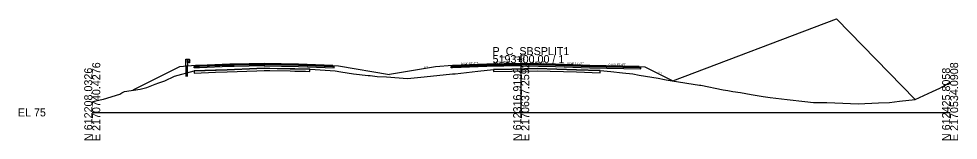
# Model space of a CAD drawing. Extents: x -26 to 1303, y -3010 to 12033.
# Drawn here: x -25.7 to 302.8, y 10990.3 to 11032.7 of the extents above; entities that cross this region are included whole.
import ezdxf

# ---------------------------------------------------------------- set-up
doc = ezdxf.new("R2010")
doc.units = 0
for name, color, linetype in [('RD_GPK_XS_Cell', 7, 'Continuous'), ('RD_PD_Final_TrvlWay', 7, 'Continuous'), ('RD_Sketch10', 7, 'Continuous'), ('RD_XS_Base', 7, 'Continuous'), ('RD_XS_ExGround', 7, 'Continuous'), ('RD_XS_ExPaveRet', 7, 'Continuous'), ('RD_XS_GR', 7, 'Continuous'), ('RD_XS_Greenside', 7, 'Continuous'), ('RD_XS_Pave', 7, 'Continuous'), ('RD_XS_PaveOvlay_CP', 7, 'Continuous'), ('RD_XS_TieSlope', 7, 'Continuous'), ('RD_XS_TX_Elev_EX', 7, 'Continuous'), ('RD_XS_TX_Elev_PR', 7, 'Continuous'), ('RD_XS_TX_Slope', 7, 'Continuous')]:
    doc.layers.add(name, color=color, linetype=linetype)

msp = doc.modelspace()

# ---------------------------------------------------------------- linework, layer by layer
at = {"layer": 'RD_GPK_XS_Cell'}
for p, q in [((150, 11000), (150, 11020)), ((0, 11000), (150, 11000)), ((150, 11000), (300, 11000))]:
    msp.add_line(p, q, dxfattribs=at)
at = {"layer": 'RD_PD_Final_TrvlWay'}
msp.add_lwpolyline([(33.27, 11012.54), (33.27, 11016.15), (32.77, 11016.11), (32.77, 11012.54)], dxfattribs=at)
at = {"layer": 'RD_Sketch10'}
msp.add_lwpolyline([(203.09, 11010.97), (260.24, 11032.67), (287.83, 11004.51)], dxfattribs=at)
at = {"layer": 'RD_XS_Base'}
for p, q in [((35.61, 11015.59), (35.61, 11016.04)), ((35.61, 11016.04), (35.67, 11016.04)), ((35.67, 11016.04), (36.11, 11016.06)), ((36.11, 11016.06), (37.5, 11016.11)), ((37.5, 11016.11), (48.11, 11016.53)), ((48.11, 11016.03), (37.5, 11015.61)), ((48.11, 11016.53), (49.67, 11016.57)), ((49.67, 11016.07), (48.11, 11016.03)), ((49.67, 11016.57), (60.11, 11016.77)), ((60.11, 11016.27), (49.67, 11016.07)), ((60.11, 11016.8), (60.11, 11016.93)), ((60.11, 11016.93), (60.11, 11016.37)), ((60.11, 11016.77), (60.11, 11016.93)), ((60.11, 11016.93), (60.11, 11016.27)), ((60.11, 11016.77), (60.11, 11016.8)), ((60.11, 11016.77), (60.11, 11016.35)), ((60.11, 11016.77), (60.11, 11016.27)), ((72.11, 11016.53), (60.11, 11016.77)), ((60.11, 11016.77), (60.11, 11016.77)), ((60.11, 11016.37), (60.11, 11016.27)), ((60.11, 11016.35), (60.11, 11016.27)), ((60.11, 11016.27), (60.11, 11016.27)), ((60.11, 11016.27), (60.11, 11016.27)), ((60.11, 11016.27), (72.11, 11016.03)), ((84.11, 11016.05), (72.11, 11016.53)), ((72.11, 11016.03), (84.61, 11015.53)), ((74.11, 11016.45), (74.11, 11016.45)), ((74.11, 11015.95), (74.11, 11015.95)), ((84.61, 11016.03), (84.11, 11016.05)), ((84.11, 11016.05), (84.11, 11016.05)), ((84.61, 11015.53), (84.61, 11016.03)), ((84.61, 11016.03), (84.61, 11016.03)), ((125.5, 11016.04), (126, 11016.06)), ((125.5, 11015.54), (125.5, 11016.04)), ((125.5, 11016.04), (125.5, 11016.04)), ((126, 11016.06), (138, 11016.54)), ((126, 11016.06), (126, 11016.06)), ((138, 11016.04), (126, 11015.56)), ((136, 11016.46), (136, 11016.46)), ((136, 11015.96), (136, 11015.96)), ((138, 11016.54), (150, 11016.78)), ((150, 11016.28), (138, 11016.04)), ((150, 11016.78), (150, 11016.94)), ((150, 11016.94), (150, 11016.28)), ((150, 11016.78), (150, 11016.78)), ((162, 11016.54), (150, 11016.78)), ((150, 11016.78), (150, 11016.78)), ((150, 11016.78), (150, 11016.28)), ((150, 11016.28), (150, 11016.28)), ((150, 11016.28), (162, 11016.04)), ((150, 11016.28), (150, 11016.28)), ((174, 11016.06), (162, 11016.54)), ((162, 11016.54), (162, 11016.54)), ((162, 11016.04), (162, 11016.04)), ((162, 11016.04), (174, 11015.56)), ((191.3, 11015.71), (174, 11016.06)), ((174, 11016.06), (174, 11016.06)), ((191.8, 11015.7), (191.3, 11015.71)), ((191.3, 11015.71), (191.3, 11015.71)), ((191.8, 11015.2), (191.8, 11015.7)), ((191.8, 11015.7), (191.8, 11015.7)), ((35.61, 11015.54), (35.61, 11015.59)), ((35.67, 11015.54), (35.61, 11015.54)), ((36.11, 11015.56), (35.67, 11015.54)), ((37.5, 11015.61), (36.11, 11015.56)), ((84.61, 11015.53), (84.61, 11015.53)), ((84.61, 11015.53), (84.61, 11015.53)), ((126, 11015.56), (125.5, 11015.54)), ((125.5, 11015.54), (125.5, 11015.54)), ((125.5, 11015.54), (125.5, 11015.54)), ((126, 11015.56), (126, 11015.56)), ((174, 11015.56), (174, 11015.56)), ((174, 11015.56), (191.8, 11015.2)), ((191.8, 11015.2), (191.8, 11015.2)), ((191.8, 11015.2), (191.8, 11015.2))]:
    msp.add_line(p, q, dxfattribs=at)
at = {"layer": 'RD_XS_ExGround'}
msp.add_lwpolyline([(0, 11003.73), (0.79, 11003.96), (2.79, 11004.34), (3.91, 11004.68), (9.65, 11006.39), (10.37, 11006.81), (10.56, 11006.9), (11.31, 11007.34), (16.71, 11008.17), (19.09, 11008.71), (22.04, 11009.82), (23.3, 11010.31), (25.38, 11011.03), (28.76, 11012.62), (35.68, 11014.46), (47.19, 11014.92), (60.12, 11015.4), (69.27, 11015.21), (76.14, 11015.07), (76.15, 11015.07), (84.95, 11014.48), (86.89, 11014.18), (91.31, 11013.5), (96.5, 11012.93), (97.15, 11012.85), (99.69, 11012.57), (102.89, 11012.43), (110.27, 11011.84), (116.03, 11012.41), (125.97, 11013.43), (126.55, 11013.47), (126.89, 11013.5), (134.83, 11014.34), (140.29, 11014.99), (146.7, 11015.1), (155.59, 11015.29), (169.3, 11014.87), (177.59, 11014.62), (181.4, 11014.23), (185.48, 11013.83), (189.04, 11013.5), (191.3, 11012.99), (197.93, 11011.9), (200.12, 11011.5), (200.7, 11011.37), (202.79, 11011.02), (212.36, 11009.52), (212.78, 11009.46), (220.69, 11007.9), (222.28, 11007.62), (224.05, 11007.3), (226.72, 11007), (230.4, 11006.28), (234.59, 11005.51), (237.06, 11005.15), (243.04, 11004.5), (249.16, 11003.79), (252.25, 11003.5), (256.89, 11003.41), (262.51, 11003.19), (267.9, 11003.05), (274.99, 11003.33), (278.83, 11003.5), (282.31, 11003.89), (287.83, 11004.51), (293.9, 11007.32), (296.44, 11008.51), (298.06, 11009.37), (300, 11010.59)], dxfattribs=at)
at = {"layer": 'RD_XS_ExPaveRet'}
for points in [[(76.14, 11015.07), (76.14, 11015.07), (74.59, 11015.1), (70.83, 11015.18), (69.27, 11015.21), (62.05, 11015.36), (60.12, 11015.4), (57.56, 11015.31), (47.19, 11014.92), (43.15, 11014.76), (35.68, 11014.46), (35.68, 11013.89), (35.68, 11013.71), (43.15, 11014.01), (47.19, 11014.17), (57.56, 11014.56), (60.12, 11014.65), (62.05, 11014.61), (69.27, 11014.46), (70.83, 11014.43), (74.59, 11014.35), (76.14, 11014.32), (76.14, 11014.32), (76.14, 11014.32), (76.14, 11014.82), (76.14, 11015.07), (76.14, 11015.07)], [(76.14, 11015.07), (74.59, 11015.1), (70.83, 11015.18), (69.27, 11015.21), (62.05, 11015.36), (60.12, 11015.4), (57.56, 11015.31), (47.19, 11014.92), (43.15, 11014.76), (35.68, 11014.46), (35.68, 11013.89), (35.68, 11013.71), (43.15, 11014.01), (47.19, 11014.17), (57.56, 11014.56), (60.12, 11014.65), (62.05, 11014.61), (69.27, 11014.46), (70.83, 11014.43), (74.59, 11014.35), (76.14, 11014.32), (76.14, 11014.82), (76.14, 11015.07)], [(169.3, 11014.87), (155.59, 11015.29), (155.59, 11015.29), (155.59, 11015.29), (146.7, 11015.1), (146.7, 11015.1), (140.29, 11014.99), (140.29, 11014.99), (140.29, 11014.24), (146.7, 11014.35), (146.7, 11014.35), (155.59, 11014.54), (155.59, 11014.54), (155.59, 11014.54), (169.3, 11014.12), (169.3, 11014.12), (177.59, 11013.87), (177.59, 11014.62), (177.59, 11014.62), (169.3, 11014.87), (169.3, 11014.87)], [(169.3, 11014.87), (155.59, 11015.29), (146.7, 11015.1), (140.29, 11014.99), (140.29, 11014.24), (146.7, 11014.35), (155.59, 11014.54), (169.3, 11014.12), (177.59, 11013.87), (177.59, 11014.62), (169.3, 11014.87)]]:
    msp.add_lwpolyline(points, dxfattribs=at)
at = {"layer": 'RD_XS_GR'}
for p, q in [((32.77, 11016.11), (32.77, 11018.54)), ((32.77, 11018.54), (33.02, 11018.54)), ((33.27, 11016.15), (32.77, 11016.11)), ((33.02, 11018.54), (33.27, 11018.54)), ((33.27, 11018.54), (33.27, 11016.15)), ((33.27, 11017.37), (33.27, 11018.54)), ((33.27, 11018.54), (33.94, 11018.54)), ((33.94, 11017.37), (33.27, 11017.37)), ((33.94, 11018.54), (33.94, 11017.37)), ((34.18, 11018.28), (33.94, 11018.54)), ((33.94, 11018.54), (33.94, 11017.51)), ((33.94, 11017.96), (33.97, 11017.99)), ((34.18, 11017.7), (33.94, 11017.96)), ((33.94, 11017.51), (33.94, 11017.37)), ((33.94, 11017.37), (33.97, 11017.41)), ((33.97, 11017.99), (34.21, 11018.25)), ((33.97, 11017.41), (34.21, 11017.67)), ((34.21, 11018.25), (34.18, 11018.28)), ((34.21, 11017.67), (34.18, 11017.7))]:
    msp.add_line(p, q, dxfattribs=at)
at = {"layer": 'RD_XS_Greenside'}
for p, q in [((30.46, 11015.92), (14.15, 11007.77)), ((86.11, 11016.21), (104, 11013.23)), ((120, 11015.9), (104, 11013.23)), ((193.3, 11015.87), (203.09, 11010.98))]:
    msp.add_line(p, q, dxfattribs=at)
at = {"layer": 'RD_XS_Pave'}
for p, q in [((37.5, 11016.43), (36.11, 11016.37)), ((36.11, 11016.37), (36.11, 11016.23)), ((37.5, 11016.27), (36.11, 11016.21)), ((36.11, 11016.21), (37.5, 11016.27)), ((36.11, 11016.23), (36.11, 11016.21)), ((36.11, 11016.21), (36.11, 11016.07)), ((36.11, 11016.06), (37.5, 11016.11)), ((36.11, 11016.07), (36.11, 11016.06)), ((48.11, 11016.85), (37.5, 11016.43)), ((48.11, 11016.69), (37.5, 11016.27)), ((37.5, 11016.27), (48.11, 11016.69)), ((37.5, 11016.11), (48.11, 11016.53)), ((49.67, 11016.88), (48.11, 11016.85)), ((49.67, 11016.73), (48.11, 11016.69)), ((48.11, 11016.69), (49.67, 11016.73)), ((48.11, 11016.53), (49.67, 11016.57)), ((60.11, 11017.09), (49.67, 11016.88)), ((60.11, 11016.93), (49.67, 11016.73)), ((49.67, 11016.73), (60.11, 11016.93)), ((49.67, 11016.57), (60.11, 11016.77)), ((72.11, 11016.85), (60.11, 11017.09)), ((60.11, 11016.8), (60.11, 11016.93)), ((60.11, 11016.93), (60.11, 11016.8)), ((60.11, 11016.77), (60.11, 11016.93)), ((60.11, 11016.93), (72.11, 11016.69)), ((72.11, 11016.69), (60.11, 11016.93)), ((60.11, 11016.93), (60.11, 11016.77)), ((60.11, 11016.77), (60.11, 11016.8)), ((60.11, 11016.8), (60.11, 11016.77)), ((60.11, 11016.77), (60.11, 11016.77)), ((60.11, 11016.77), (60.11, 11016.77)), ((60.11, 11016.77), (72.11, 11016.53)), ((84.11, 11016.37), (72.11, 11016.85)), ((72.11, 11016.69), (84.11, 11016.21)), ((84.11, 11016.21), (72.11, 11016.69)), ((72.11, 11016.53), (84.11, 11016.05)), ((74.11, 11016.77), (74.11, 11016.77)), ((74.11, 11016.61), (74.11, 11016.61)), ((74.11, 11016.61), (74.11, 11016.61)), ((74.11, 11016.45), (74.11, 11016.45)), ((84.11, 11016.21), (84.11, 11016.37)), ((84.11, 11016.37), (84.11, 11016.37)), ((84.11, 11016.21), (84.11, 11016.21)), ((84.11, 11016.21), (84.11, 11016.21)), ((84.11, 11016.05), (84.11, 11016.21)), ((84.11, 11016.21), (84.11, 11016.21)), ((84.11, 11016.05), (84.11, 11016.05)), ((84.11, 11016.05), (84.11, 11016.05)), ((138, 11016.86), (126, 11016.38)), ((138, 11016.7), (126, 11016.22)), ((126, 11016.22), (138, 11016.7)), ((126, 11016.06), (138, 11016.54)), ((126, 11016.38), (126, 11016.38)), ((126, 11016.38), (126, 11016.22)), ((126, 11016.22), (126, 11016.22)), ((126, 11016.22), (126, 11016.06)), ((126, 11016.22), (126, 11016.22)), ((126, 11016.22), (126, 11016.22)), ((126, 11016.06), (126, 11016.06)), ((126, 11016.06), (126, 11016.06)), ((136, 11016.78), (136, 11016.78)), ((136, 11016.62), (136, 11016.62)), ((136, 11016.62), (136, 11016.62)), ((136, 11016.46), (136, 11016.46)), ((150, 11017.1), (138, 11016.86)), ((150, 11016.94), (138, 11016.7)), ((138, 11016.7), (150, 11016.94)), ((138, 11016.54), (150, 11016.78)), ((162, 11016.86), (150, 11017.1)), ((150, 11016.78), (150, 11016.94)), ((150, 11016.94), (162, 11016.7)), ((162, 11016.7), (150, 11016.94)), ((150, 11016.94), (150, 11016.94)), ((150, 11016.94), (150, 11016.78)), ((150, 11016.78), (150, 11016.78)), ((150, 11016.78), (150, 11016.78)), ((150, 11016.78), (150, 11016.78)), ((150, 11016.78), (162, 11016.54)), ((174, 11016.38), (162, 11016.86)), ((162, 11016.86), (162, 11016.86)), ((162, 11016.7), (162, 11016.7)), ((162, 11016.7), (174, 11016.22)), ((174, 11016.22), (162, 11016.7)), ((162, 11016.7), (162, 11016.7)), ((162, 11016.54), (162, 11016.54)), ((162, 11016.54), (174, 11016.06)), ((191.3, 11016.03), (174, 11016.38)), ((174, 11016.38), (174, 11016.38)), ((174, 11016.22), (174, 11016.22)), ((174, 11016.22), (191.3, 11015.87)), ((191.3, 11015.87), (174, 11016.22)), ((174, 11016.22), (174, 11016.22)), ((174, 11016.06), (174, 11016.06)), ((174, 11016.06), (191.3, 11015.71)), ((191.3, 11015.87), (191.3, 11016.03)), ((191.3, 11016.03), (191.3, 11016.03)), ((191.3, 11015.87), (191.3, 11015.87)), ((191.3, 11015.87), (191.3, 11015.87)), ((191.3, 11015.71), (191.3, 11015.87)), ((191.3, 11015.87), (191.3, 11015.87)), ((191.3, 11015.71), (191.3, 11015.71)), ((191.3, 11015.71), (191.3, 11015.71))]:
    msp.add_line(p, q, dxfattribs=at)
at = {"layer": 'RD_XS_PaveOvlay_CP'}
for p, q in [((36.11, 11016.37), (48.11, 11016.85)), ((48.11, 11016.85), (60.11, 11017.09)), ((60.11, 11017.09), (72.11, 11016.85)), ((72.11, 11016.85), (84.11, 11016.37)), ((138, 11016.86), (126, 11016.38)), ((126, 11016.38), (126, 11016.38)), ((136, 11016.78), (136, 11016.78)), ((150, 11017.1), (138, 11016.86)), ((162, 11016.86), (150, 11017.1)), ((174, 11016.38), (162, 11016.86)), ((162, 11016.86), (162, 11016.86)), ((191.3, 11016.03), (174, 11016.38)), ((174, 11016.38), (174, 11016.38)), ((191.3, 11016.03), (191.3, 11016.03))]:
    msp.add_line(p, q, dxfattribs=at)
at = {"layer": 'RD_XS_TieSlope'}
for p, q in [((36.11, 11016.37), (30.46, 11015.92)), ((84.11, 11016.37), (86.11, 11016.21)), ((126, 11016.38), (120, 11015.9)), ((191.3, 11016.03), (193.3, 11015.87))]:
    msp.add_line(p, q, dxfattribs=at)

# ---------------------------------------------------------------- texts
at = {"layer": 'RD_GPK_XS_Cell'}
for s, p in [('P_C_SBSPLIT1', (140, 11020)), ('5193+00.00 / 1', (140, 11017.2)), ('EL 75', (-26, 10998.6))]:
    msp.add_text(s, height=2.8, dxfattribs=at).set_placement(p)
for s, p in [('E 2170740.4276', (2.8, 10990)), ('E 2170637.2592', (152.8, 10990)), ('E 2170534.0908', (302.8, 10990)), ('N 612208.0326', (0, 10990)), ('N 612316.9192', (150, 10990)), ('N 612425.8058', (300, 10990))]:
    msp.add_text(s, height=2.8, rotation=90, dxfattribs=at).set_placement(p)
at = {"layer": 'RD_XS_TX_Elev_EX'}
msp.add_text('90.17', height=0.6, rotation=90, dxfattribs=at).set_placement((149.66, 11017.7))
at = {"layer": 'RD_XS_TX_Elev_PR'}
msp.add_text('92.10', height=1, rotation=90, dxfattribs=at).set_placement((151.18, 11017.38))
at = {"layer": 'RD_XS_TX_Slope'}
for s, rotation, p in [('6:1', 9.4623, (116.13, 11015.31)), ('0.040 FT./FT.', 2.2906, (128.93, 11016.59)), ('0.020 FT./FT.', 1.1458, (140.27, 11017.07)), ('0.020 FT./FT.', 358.8542, (153.94, 11017.12)), ('0.040 FT./FT.', 357.7094, (165.94, 11016.8)), ('0.020 FT./FT.', 358.8542, (180.59, 11016.34)), ('2:1', 333.4349, (197.77, 11013.7))]:
    msp.add_text(s, height=0.75, rotation=rotation, dxfattribs=at).set_placement(p)

doc.saveas('drawing.dxf')
